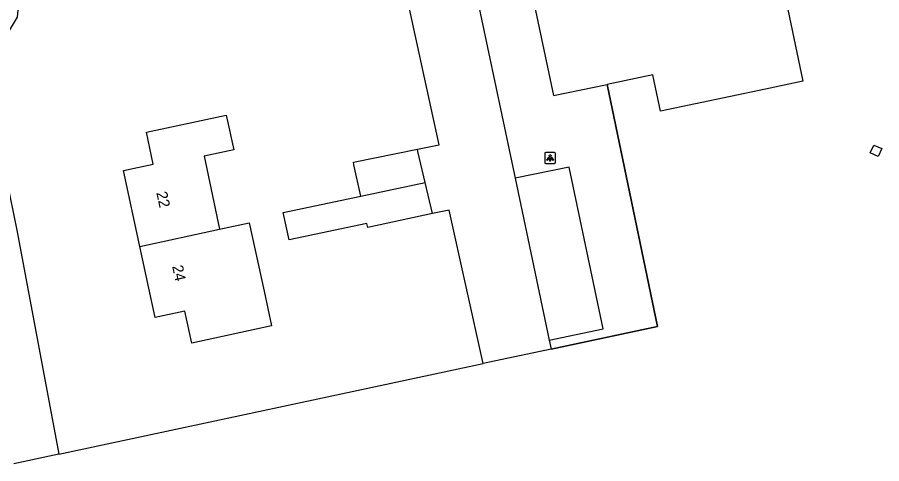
# Model space of a CAD drawing. Extents: x 164494 to 166241, y 382475 to 384494.
# Drawn here: x 164931.2 to 165010.7, y 384284.2 to 384325.2 of the extents above; entities that cross this region are included whole.
import ezdxf

# ---------------------------------------------------------------- set-up
doc = ezdxf.new("R2010")
doc.units = 0
for name, color, linetype in [('IMGEO_Groenvoorziening', 7, 'Continuous'), ('IMGEO_Hek', 7, 'Continuous'), ('IMGEO_Hoogspanningsmast', 7, 'Continuous'), ('IMGEO_Lichtpunt', 7, 'Continuous'), ('IMGEO_Pand', 7, 'Continuous'), ('IMGEO_Pand_nummerreeks', 7, 'Continuous'), ('IMGEO_Parkeervlak_open', 7, 'Continuous'), ('IMGEO_Rijbaan_lokaal_open', 7, 'Continuous')]:
    doc.layers.add(name, color=color, linetype=linetype)

msp = doc.modelspace()

# ---------------------------------------------------------------- linework, layer by layer
at = {"layer": 'IMGEO_Groenvoorziening'}
msp.add_lwpolyline([(164985.443, 384319.065), (164990.062, 384296.82), (164980.294, 384294.743)], dxfattribs=at)
at = {"layer": 'IMGEO_Hek'}
for points in [[(164980.294, 384294.743), (164990.062, 384296.82), (164985.443, 384319.065)], [(164935.029, 384285.096), (164974.03, 384293.405)]]:
    msp.add_lwpolyline(points, dxfattribs=at)
at = {"layer": 'IMGEO_Hoogspanningsmast'}
msp.add_lwpolyline([(165009.635, 384312.76), (165009.956, 384313.493), (165010.689, 384313.172), (165010.368, 384312.439), (165009.635, 384312.76)], dxfattribs=at)
at = {"layer": 'IMGEO_Lichtpunt'}
for p, q in [((164979.698, 384312.709), (164979.698, 384311.902)), ((164979.698, 384312.709), (164979.698, 384311.902)), ((164980.6, 384312.804), (164979.792, 384312.804)), ((164980.6, 384312.804), (164979.792, 384312.804)), ((164980.694, 384311.902), (164980.694, 384312.709)), ((164980.694, 384311.902), (164980.694, 384312.709)), ((164979.792, 384311.808), (164980.6, 384311.808)), ((164979.792, 384311.808), (164980.6, 384311.808))]:
    msp.add_line(p, q, dxfattribs=at)
for points in [[(164980.072, 384312.373), (164980.111, 384312.345), (164979.923, 384312.083), (164979.885, 384312.11), (164980.072, 384312.373)], [(164980.174, 384312.325), (164980.221, 384312.325), (164980.221, 384312.003), (164980.174, 384312.003), (164980.174, 384312.325)], [(164980.284, 384312.345), (164980.322, 384312.372), (164980.509, 384312.11), (164980.47, 384312.082), (164980.284, 384312.345)]]:
    msp.add_lwpolyline(points, dxfattribs=at)
msp.add_circle((164980.197, 384312.507), 0.0994, dxfattribs=at)
for centre, start, end in [((164979.792, 384312.709), 90, 180), ((164979.792, 384312.709), 90, 180), ((164980.6, 384312.709), 0, 90), ((164980.6, 384312.709), 0, 90), ((164979.792, 384311.902), 180, 270), ((164979.792, 384311.902), 180, 270), ((164980.6, 384311.902), 270, 0), ((164980.6, 384311.902), 270, 360)]:
    msp.add_arc(centre, 0.0946, start, end, dxfattribs=at)
at = {"layer": 'IMGEO_Pand'}
for points in [[(165000.234, 384334.604), (165003.425, 384319.356), (165000, 384318.639), (164990.338, 384316.617), (164989.641, 384319.943), (164985.443, 384319.065)], [(164987.642, 384331.969), (164987.069, 384331.849), (164987.376, 384330.38), (164978.312, 384328.483), (164980.499, 384318.03), (164985.443, 384319.065)], [(164942.459, 384304.183), (164940.961, 384311.148), (164943.699, 384311.737), (164943.069, 384314.67), (164950.412, 384316.25), (164951.1, 384313.054), (164948.373, 384312.468), (164949.804, 384305.763)], [(164962.793, 384308.801), (164962.158, 384311.679), (164962.107, 384311.911), (164967.996, 384313.104)], [(164968.719, 384310.043), (164968.046, 384312.894), (164967.996, 384313.104)], [(164962.793, 384308.801), (164968.719, 384310.043)], [(164969.392, 384307.192), (164968.719, 384310.043)], [(164969.392, 384307.192), (164963.428, 384305.923), (164963.349, 384306.281), (164956.184, 384304.779), (164955.655, 384307.305), (164962.793, 384308.801)], [(164949.804, 384305.763), (164952.532, 384306.349), (164953.886, 384300.05), (164954.569, 384296.872), (164947.236, 384295.294), (164946.605, 384298.226), (164943.867, 384297.637), (164942.459, 384304.183)], [(164942.459, 384304.183), (164949.804, 384305.763)]]:
    msp.add_lwpolyline(points, dxfattribs=at)
at = {"layer": 'IMGEO_Parkeervlak_open'}
msp.add_lwpolyline([(164980.116, 384295.575), (164985.086, 384296.596), (164981.938, 384311.469), (164976.99, 384310.432)], dxfattribs=at)
at = {"layer": 'IMGEO_Rijbaan_lokaal_open'}
for points in [[(164976.708, 384339.106), (164972.661, 384333.951), (164973.308, 384330.982), (164972.656, 384330.873), (164976.99, 384310.432)], [(164967.996, 384313.104), (164968.93, 384313.293), (164969.978, 384313.506), (164966.532, 384329.404), (164965.642, 384329.426), (164965.275, 384332.269), (164960.93, 384335.824)], [(164931.595, 384329.704), (164931.189, 384325.235), (164929.571, 384322.569), (164928.461, 384318.744), (164931.192, 384305.516), (164935.029, 384285.096), (164930.87, 384284.21)], [(164976.99, 384310.432), (164980.116, 384295.575)], [(164980.294, 384294.743), (164974.03, 384293.405), (164970.898, 384307.493), (164969.392, 384307.192)], [(164980.116, 384295.575), (164980.294, 384294.743)]]:
    msp.add_lwpolyline(points, dxfattribs=at)

# ---------------------------------------------------------------- texts
at = {"layer": 'IMGEO_Pand_nummerreeks'}
for s, p in [('22', (164943.977, 384309.111)), ('24', (164945.431, 384302.353))]:
    msp.add_text(s, height=1, rotation=282.13848, dxfattribs=at).set_placement(p)

doc.saveas('drawing.dxf')
